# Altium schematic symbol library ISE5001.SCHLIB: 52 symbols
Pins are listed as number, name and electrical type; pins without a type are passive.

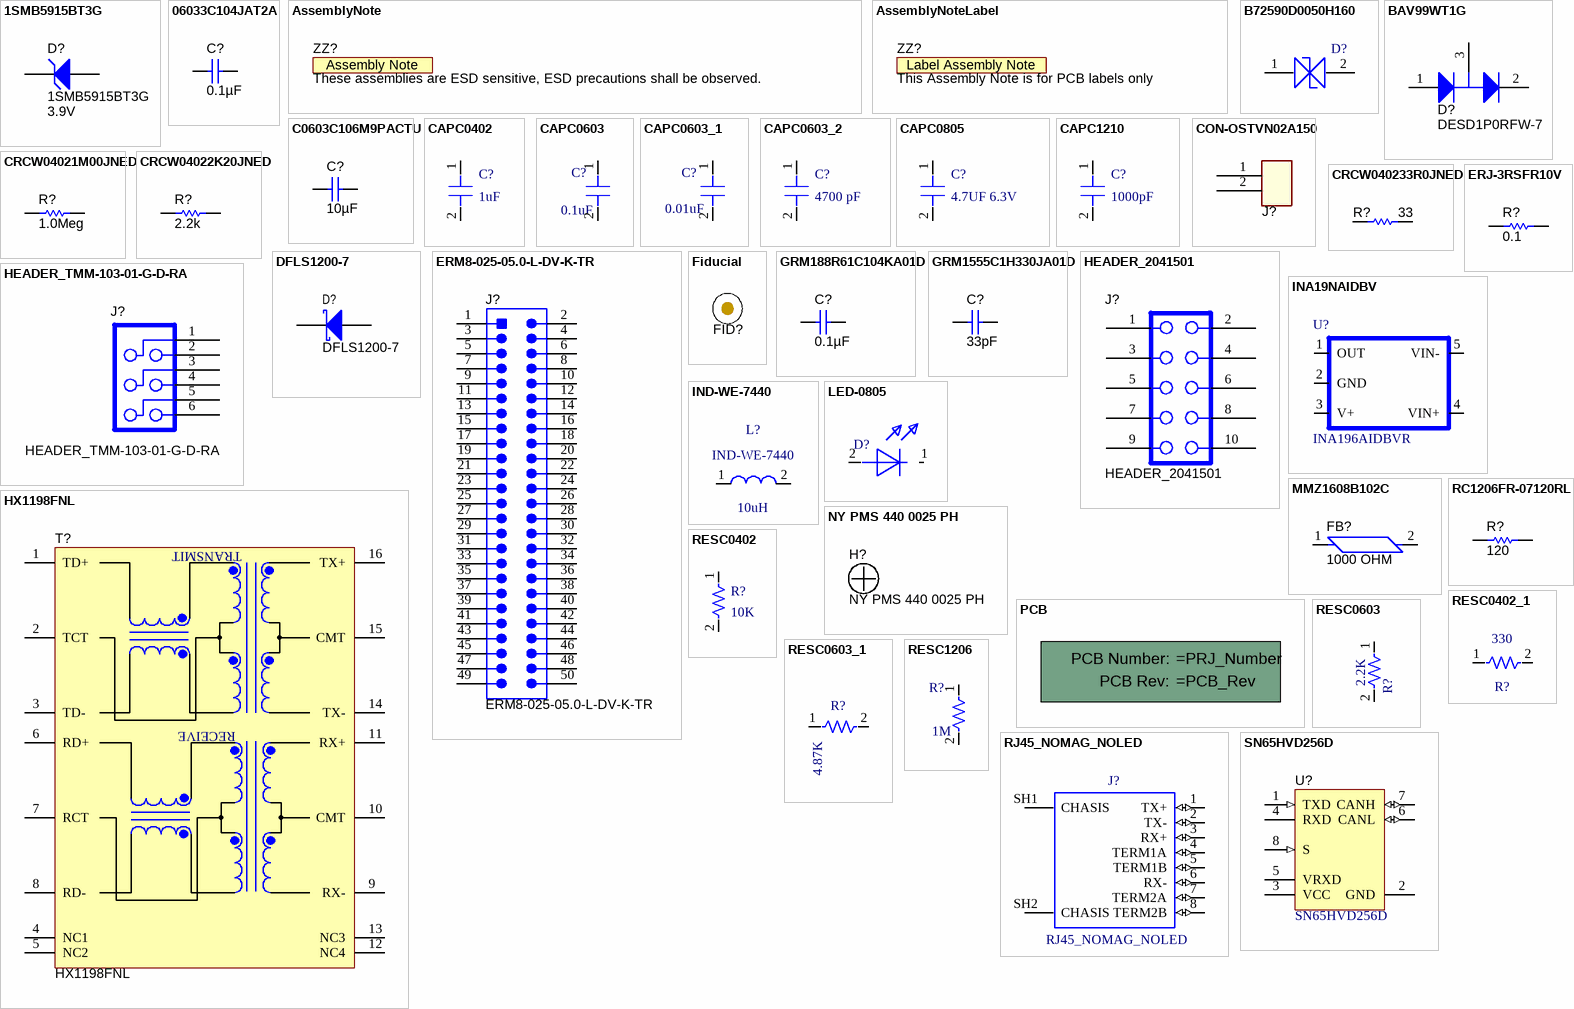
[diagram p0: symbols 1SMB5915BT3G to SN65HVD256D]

## 1SMB5915BT3G
designator D?  value 3.9V
Diode, Zener, 3.9V, 550mW, SMB; Manufacturer: ON Semiconductor; SymbolCreator: a0412235; U/M: EA; Power_W: 0.55; Vz_V: 3.9; Value1: 0.55W; RJA_CperW: 226
signal-integrity model Diode
footprint SMB
pins: 1 K, 2 A

## 06033C104JAT2A
designator C?  ValueDisplayed: 0.1µF  (hidden comment: 06033C104JAT2A)
CAP, CERM, 0.1uF, 25V, +/-5%, X7R, 0603; Manufacturer: AVX; Polarized: N; CompType: Capacitor; U/M: EA; Cap_F: 0.0000001; Tolerance_%: 5; ESR_Ohm: 0.05; Value1: 0.05 ohm; VDC_V: 25; TaMin_C: -55; TaMax_C: 125; Cap_Case: 0603
signal-integrity model Cap
simulation model Cap
footprint 0603
footprint 0603M
footprint 0603L
footprint 0603_HV
pins: 1, 2

## AssemblyNote
designator ZZ?, comment These assemblies are ESD sensitive, ESD precautions shall be observed.  (no BOM)
SymbolCreator: codlsc; CompType: AssemblyNote
footprint AssemblyNote

## AssemblyNoteLabel
designator ZZ?, comment This Assembly Note is for PCB labels only  (no BOM)
SymbolCreator: a0412235
footprint AssemblyNoteLabel

## B72590D0050H160
designator D?  (value not drawn)
Diode, 5.6V ESD Suppressor 0402; GNUM: G14-D0402-5V6-DAA; PCB DECAL: RESC0402N
footprint RESC0402N
pins: 1 (power), 2

## BAV99WT1G
designator D?, comment DESD1P0RFW-7
Diode, P-N, 70V, 0.2A, SOT-323; Manufacturer: Diodes Inc
footprint SOT-323
pins: 1 A, 2 K, 3 C
1 alternate drawing of the same symbol

## C0603C106M9PACTU
designator C?  ValueDisplayed: 10µF  (hidden comment: C0603C106M9PACTU)
CAP, CERM, 10uF, 6.3V, +/-20%, X5R, 0603; Manufacturer: Kemet; Polarized: N; CompType: Capacitor; U/M: EA; Cap_F: 0.00001; Tolerance_%: 20; ESR_Ohm: 0.004; Value1: 0.004 ohm; VDC_V: 6.3; IRMS_A: 8.9; TaMin_C: -55; TaMax_C: 85; Cap_Case: 0603
signal-integrity model Cap
simulation model Cap
footprint 0603
footprint 0603M
footprint 0603L
footprint 0603_HV
pins: 1, 2

## CAPC0402
designator C?  value 1uF  (hidden comment: CAPC0402)
Capacitor, 1uF , X5R, 10V, 0402; Part Number: C1005X5R1A105M050BB; PCB DECAL: CAPC0402N; GNUM: G10-C0402-C105-GCB
footprint 0402 (0402 from SM-752 data)
pins: 1, 2

## CAPC0603
designator C?  value 0.1uF  (hidden comment: CAPC0603)
Capacitor, 0.1uF 50V, 20% 0603 X7R; Part Number: C1608X7R1H104M; GNUM: G10-C0603-C104-ACA; PCB DECAL: CAPC0603L
footprint 0603 (0603 from SM-752 data)
pins: 1, 2

## CAPC0603_1
designator C?, comment value 0.01uF  (hidden comment: CAPC0603)
Capacitor, 0.01uF 25V, 10% 0402 X7R; Part Number: TMK105B7103KV-F; PCB DECAL: CAPC0402L; GNUM: G10-C0402-C103-BBA
footprint 0402 (0402 from SM-752 data)
pins: 1, 2

## CAPC0603_2
designator C?, comment value 4700 pF  (hidden comment: CAPC0603)
Capacitor, 4700pF, 2kV, 10%, X7R, 1812; Part Number: 1812GC472KAT1A; GNUM: G10-C1812-C472-ZBA; PCB DECAL: 1812MIL
footprint 1812
pins: 1, 2

## CAPC0805
designator C?  value 4.7UF 6.3V  (hidden comment: CAPC0805)
Capacitor, 4.7uF, 6.3V, 10% 0805, X5R; Part Number: JMK212BJ475KG-T; GNUM: G10-C0805-C475-DBB; Geometry.Height: 1.1mm; PCBL.Component: CHP;CAPC;1800;2200;250;750;1050;1450;1100; PCBL.Process: F;N;50;50;200;100;200;250;350;-50;0
footprint 0805 (0805 from SM-752 data)
pins: 1, 2

## CAPC1210
designator C?  value 1000pF  (hidden comment: CAPC1210)
CAP CER 1000PF 2KV 20% X7R 1210; Part Number: C1210C102MGRACTU; GNUM: G10-C1210-C102-ZCA
footprint 1210 (1210 from SM-752 data)
pins: 1, 2

## CON-OSTVN02A150
designator J?  (value not drawn)
Terminal Block, 4x1, 2.54mm, TH; Manufacturer: On Shore Technology Inc; SymbolCreator: x0120606
footprint CN2_MTB_P100_PD80_D1.1_S5.54X6.5_STACK
pins: 1, 2

## CRCW04021M00JNED
designator R?  value 1.0Meg  (hidden comment: CRCW04021M00JNED)
RES, 1.0Meg ohm, 5%, 0.063W, 0402; Manufacturer: Vishay-Dale; CompType: Resistor; Res_ohm: 1000000; Value_Code: 1M00; Tolerance_%: 5; Power_W: 0.063; VDC_V: 50; TempCo: 200 ppm/C; EIA_Code: E24; U/M: EA
signal-integrity model Resistor
simulation model Resistor
footprint 0402
footprint 0402M
footprint 0402L
footprint 0402S
pins: 1, 2

## CRCW04022K20JNED
designator R?  value 2.2k  (hidden comment: CRCW04022K20JNED)
RES, 2.2k ohm, 5%, 0.063W, 0402; Manufacturer: Vishay-Dale; CompType: Resistor; Res_ohm: 2200; Value_Code: 2k20; Tolerance_%: 5; Power_W: 0.063; VDC_V: 50; TempCo: 200 ppm/C; EIA_Code: E24; U/M: EA
signal-integrity model Resistor
simulation model Resistor
footprint 0402
footprint 0402M
footprint 0402L
footprint 0402S
pins: 1, 2

## CRCW040233R0JNED
designator R?  value 33  (hidden comment: CRCW040233R0JNED)
RES, 33 ohm, 5%, 0.063W, 0402; Manufacturer: Vishay-Dale; CompType: Resistor; Value_Code: 33R0; Tolerance_%: 5; Power_W: 0.063; VDC_V: 50; TempCo: 200 ppm/C; EIA_Code: E24; U/M: EA
signal-integrity model Resistor
simulation model Resistor
footprint 0402
footprint 0402M
footprint 0402L
footprint 0402S
pins: 1, 2

## DFLS1200-7
designator D?
Diode, Schottky, 200V, 1A, PowerDI123; Manufacturer: Diodes Inc.; U/M: EA; Vf_V: 0.85; Value2: 0.85V; Io_A: 1; Vr_V: 200; TJmax_C: 175; RJC_CperW: 7
signal-integrity model Diode
simulation model DI_DFLS1200
footprint powerDI123
pins: 1 K, 2 A

## ERJ-3RSFR10V
designator R?  value 0.1  (hidden comment: ERJ-3RSFR10V)
RES, 0.1 ohm, 1%, 0.1W, 0603; Manufacturer: Panasonic; CompType: Resistor; Value_Code: R100; Tolerance_%: 1; TempCo: 300 ppm/C; EIA_Code: E96; U/M: EA
signal-integrity model Resistor
simulation model Resistor
footprint 0603 (0603 from SM-752 data)
pins: 1, 2

## ERM8-025-05.0-L-DV-K-TR
designator J?
CONN MICRO HS TERM STRP HDR 50 POS; Manufacturer: Samtec; SymbolCreator: a0799628; CompType: Header; U/M: EA
footprint SAMTEC_ERM8-025-05_0-L-DV-K-TR
pins: 1, 2, 3, 4, 5, 6, 7, 8, 9, 10, 11, 12, 13, 14, 15, 16, 17, 18, 19, 20, 21, 22, 23, 24, 25, 26, 27, 28, 29, 30, 31, 32, 33, 34, 35, 36, 37, 38, 39, 40, 41, 42, 43, 44, 45, 46, 47, 48, 49, 50

## Fiducial
designator FID?  (value not drawn)
Fiducial mark.  There is nothing to buy or mount.; SymbolCreator: codlsc
footprint Fiducial10-30
footprint Fiducial10-20
footprint Fiducial15-30
footprint Fiducial20-40
footprint Fiducial6.4-20
footprint Fiducial10-30_TopLayerKeepOutOnly
footprint Fiducial6.4-20_TopLayerKeepOutOnly
footprint Fiducial10-20_TopLayerKeepOutOnly
footprint Fiducial15-30_TopLayerKeepOutOnly
footprint Fiducial20-40_TopLayerKeepOutOnly

## GRM188R61C104KA01D
designator C?  ValueDisplayed: 0.1µF  (hidden comment: GRM188R61C104KA01D)
CAP, CERM, 0.1uF, 16V, +/-10%, X5R, 0603; Manufacturer: MuRata; Polarized: N; CompType: Capacitor; U/M: EA; Cap_F: 0.0000001; Tolerance_%: 10; Value1: Unknown; VDC_V: 16; TaMin_C: -55; TaMax_C: 85; Cap_Case: 0603
signal-integrity model Cap
simulation model Cap
footprint 0603
footprint 0603M
footprint 0603L
footprint 0603_HV
pins: 1, 2

## GRM1555C1H330JA01D
designator C?  ValueDisplayed: 33pF  (hidden comment: GRM1555C1H330JA01D)
CAP, CERM, 33pF, 50V, +/-5%, C0G/NP0, 0402; Manufacturer: MuRata; Polarized: N; CompType: Capacitor; U/M: EA; Cap_F: 0.000000000033; Tolerance_%: 5; Value1: Unknown; VDC_V: 50; TaMin_C: -55; TaMax_C: 125; Cap_Case: 0402
signal-integrity model Cap
simulation model Cap
footprint 0402
footprint 0402M
footprint 0402L
footprint 0402S
pins: 1, 2

## HEADER_2041501
designator J?
Header, 2X5 2mm spacing; PartNumber: M22-2020505; Manufacturer: Harwin Inc; Area: 55 mm
footprint HDR_2X5-2MM
pins: 1, 2, 3, 4, 5, 6, 7, 8, 9, 10

## HEADER_TMM-103-01-G-D-RA
designator J?
Header, 2mm, Low Profile 2x3; Manufacturer: Samtec; Area: 57.75 mm
footprint HEADER_TMM-103[2X]
pins: 1, 2, 3, 4, 5, 6

## HX1198FNL
designator T?
TRANSFORMER, MDL, XFMR SGL ETHR LAN, SOIC-16; Manufacturer: PULSE ELECTRONICS; SymbolCreator: x0199378
footprint XFMR_ HX1198FNL (TRANSFORMER, MODULE XFMR, 16-SOIC)
pins: 1 TD+, 2 TCT, 3 TD-, 4 NC1, 5 NC2, 6 RD+, 7 RCT, 8 RD-, 9 RX-, 10 CMT, 11 RX+, 12 NC4, 13 NC3, 14 TX-, 15 CMT, 16 TX+

## INA19NAIDBV
designator U?, comment INA196AIDBVR
IC, Current Shunt Monitor, -16V to 80V Common-Mode Range; Manufacturer: TI; Alternate Manufacturer: None; Area: 23200; Value: INA196/8AIDBV; PCB DECAL: REF3230AIDBVT
footprint SOT23-5P
pins: 1 OUT, 2 GND, 3 V+, 4 VIN+, 5 VIN-

## IND-WE-7440
designator L?  value 10uH
Inductor 10uH, SMD 2.8x2.8mm, 0.5A, 0.47 Ohm; Part Number: 744029100; GNUM: G12-SM2X2-I100-ADA; PCB DECAL: IND-WE-2M8
footprint IND_744029100 (INDUCTOR , SMD 2.8X2.8MM)
pins: 1, 2

## LED-0805
designator D?  (value not drawn)
LED AMBER CLEAR 0805 SMD; Manufacturer #1: LITE-ON; Part Number: LTST-C170AKT; PCB DECAL: DIOC0805N; GNUM: G14-D0805-AMB0-AAA; Description: SMT LED IN 0805 PACK
footprint DIOC0805N
pins: 1, 2

## MMZ1608B102C
designator FB?, comment 1000 OHM
FERRITE CHIP 1000 OHM 300MA 0603; PartNumber: MMZ1608B102C; Manufacturer: TDK Corporation; CompType: Ferrite Bead
footprint 0603L (0603 from SM-752 data)
pins: 1, 2

## NY PMS 440 0025 PH
designator H?
Machine Screw, Round, #4-40 x 1/4, Nylon, Philips panhead; Manufacturer: B&F Fastener Supply; CompType: Hardware; SymbolCreator: codlsc; U/M: EA
footprint MH3.2_H5_W6_KO8_STARHEAD

## PCB
designator !PCB?, comment Printed Circuit Board  (value not drawn)  (mechanical)
Manufacturer: Any; SymbolCreator: a0412235; CompType: PCB
1 alternate drawing of the same symbol

## RC1206FR-07120RL
designator R?  value 120  (hidden comment: RC1206FR-07120RL)
RES, 120 ohm, 1%, 0.25W, 1206; Manufacturer: Yageo America; CompType: Resistor; Value_Code: 120R; Tolerance_%: 1; Power_W: 0.25; VDC_V: 200; TempCo: 100 ppm/C; U/M: EA
signal-integrity model Resistor
simulation model Resistor
footprint 1206
footprint 1206M
footprint 1206L
pins: 1, 2

## RESC0402
designator R?  value 10K  (hidden comment: RESC0402)
Resistor, 10k ohm, 1/10W, 5%, 0402 Thick Film; Manufacturer #1: Generic; Part Number: RC0402FR-0710KL; Also Known As: 0402; Description: Resistor,Chip;1.00mm L X 0.5mm W X 0.35mm H; Geometry.Height: 0.35mm; PCBL.Component: CHP;RESC;1500;1700;150;400;700;950;600; PCBL.Process: F;N;50;50;200;100;200;250;350;-50;0; PCB DECAL: RESC0402N; GNUM: G11-R0402-1002-AAA
footprint 0402 (0402 from SM-752 data)
pins: 1, 2

## RESC0402_1
designator R?, comment value 330  (hidden comment: RESC0402)
Resistor, 330 ohm, 1/10W, 5%, 0402; Manufacturer #1: Generic; Part Number: RC0402FR-07330RL; Also Known As: 0402; Description: Resistor,Chip;1.00mm L X 0.5mm W X 0.35mm H; Geometry.Height: 0.35mm; PCBL.Component: CHP;RESC;1500;1700;150;400;700;950;600; PCBL.Process: F;N;50;50;200;100;200;250;350;-50;0; PCB DECAL: RESC0402N; GNUM: G11-R0402-3300-AAA
footprint 0402 (0402 from SM-752 data)
pins: 1, 2

## RESC0603
designator R?  value 2.2K  (hidden comment: RESC0603)
Resistor, 2.2K OHM 1/10W 5% 0603 SMD; Manufacturer #1: Generic; Part Number: CRCW06032K20JNEA; PCB DECAL: RESC0603N; GNUM: G11-R0603-R222-AAA; Also Known As: 0603; Description: Resistor,Chip;1.60mm L X 0.83mm W X 0.60mm H; Geometry.Height: 0.6mm; PCBL.Component: CHP;RESC;1500;1700;150;400;700;950;600; PCBL.Process: F;N;50;50;200;100;200;250;350;-50;0
footprint 0603 (0603 from SM-752 data)
pins: 1, 2

## RESC0603_1
designator R?, comment value 4.87K  (hidden comment: RESC0603)
Resistor, 4.87K Ohm, 1/10W, 1%, SMD, Thick; Manufacturer #1: Generic; Part Number: ERJ-3EKF4871V; Also Known As: 0603; Description: Resistor,Chip;1.60mm L X 0.83mm W X 0.60mm H; Geometry.Height: 0.6mm; PCBL.Component: CHP;RESC;1500;1700;150;400;700;950;600; PCBL.Process: F;N;50;50;200;100;200;250;350;-50;0; PCB DECAL: RESC0603N; GNUM: G11-R0603-4871-ABA
footprint 0603 (0603 from SM-752 data)
pins: 1, 2

## RESC1206
designator R?  value 1M  (hidden comment: RESC1206)
RES 1M OHM 5% 1206 TF; Manufacturer #1: IPC SM-782; Part Number: ERJ-8GEYJ105V; Description: SURFACE MOUNT RESISTOR OR CAPACITOR 0.062 X 0.126 INCHES; PCB DECAL: 1206; GNUM: G11-R1206-R105-CAA
footprint 1206
pins: 1, 2

## RJ45_NOMAG_NOLED
designator J?
Connector, RJ45 NO MAG, shielded THRU HOLE; Part Number: 6116526-1; PCB DECAL: 406541; GNUM: G20-8RJ45-ENET-AAA
footprint TE_6116526-1 (CONNECTOR, MODULAR JACK SHIELDED R/A, THRU-8 PIN)
pins: 1 TX+ (io), 2 TX- (io), 3 RX+ (io), 4 TERM1A (io), 5 TERM1B (io), 6 RX- (io), 7 TERM2A (io), 8 TERM2B (io), SH1 CHASIS, SH2 CHASIS

## SN65HVD256D
designator U?
CAN Transceiver with Fast Loop Times for Highly Loaded Networks, 85 mA, 5 V, -40 to 125 degC, 8-pin SOIC (D), Green (RoHS & no Sb/Br); Manufacturer: Texas Instruments; Alternate Manufacturer: None; Alternate PartNumber: Equivalent; Drivers Per Package: 1; Bus Fault Voltage(V): -27 to 40; ICC(Max)(mA): 85; Supply Voltage(s)(V): 5; Rating: Catalog
footprint D0008A_N (SOIC, 8-Leads, Body 4.9x3.9mm, Pitch 1.27mm, IPC Medium Density)
footprint D0008A_L (SOIC, 8-Leads, Body 4.9x3.9mm, Pitch 1.27mm, IPC High Density)
footprint D0008A_M (SOIC, 8-Leads, Body 4.9x3.9mm, Pitch 1.27mm, IPC Low Density)
pins: 1 TXD (in) "CAN transmit data input (LOW for dominant and HIGH for recessive bus states)", 2 GND (power) "Ground connection", 3 VCC (power) "Transceiver 5V supply voltage", 4 RXD (hiz) "CAN receive data output (LOW for dominant and HIGH for recessive bus states)", 5 VRXD (power) "RXD output supply voltage", 6 CANL (io) "Low level CAN bus line", 7 CANH (io) "High level CAN bus line", 8 S (in) "S (Silent Mode) select pin (active high)"

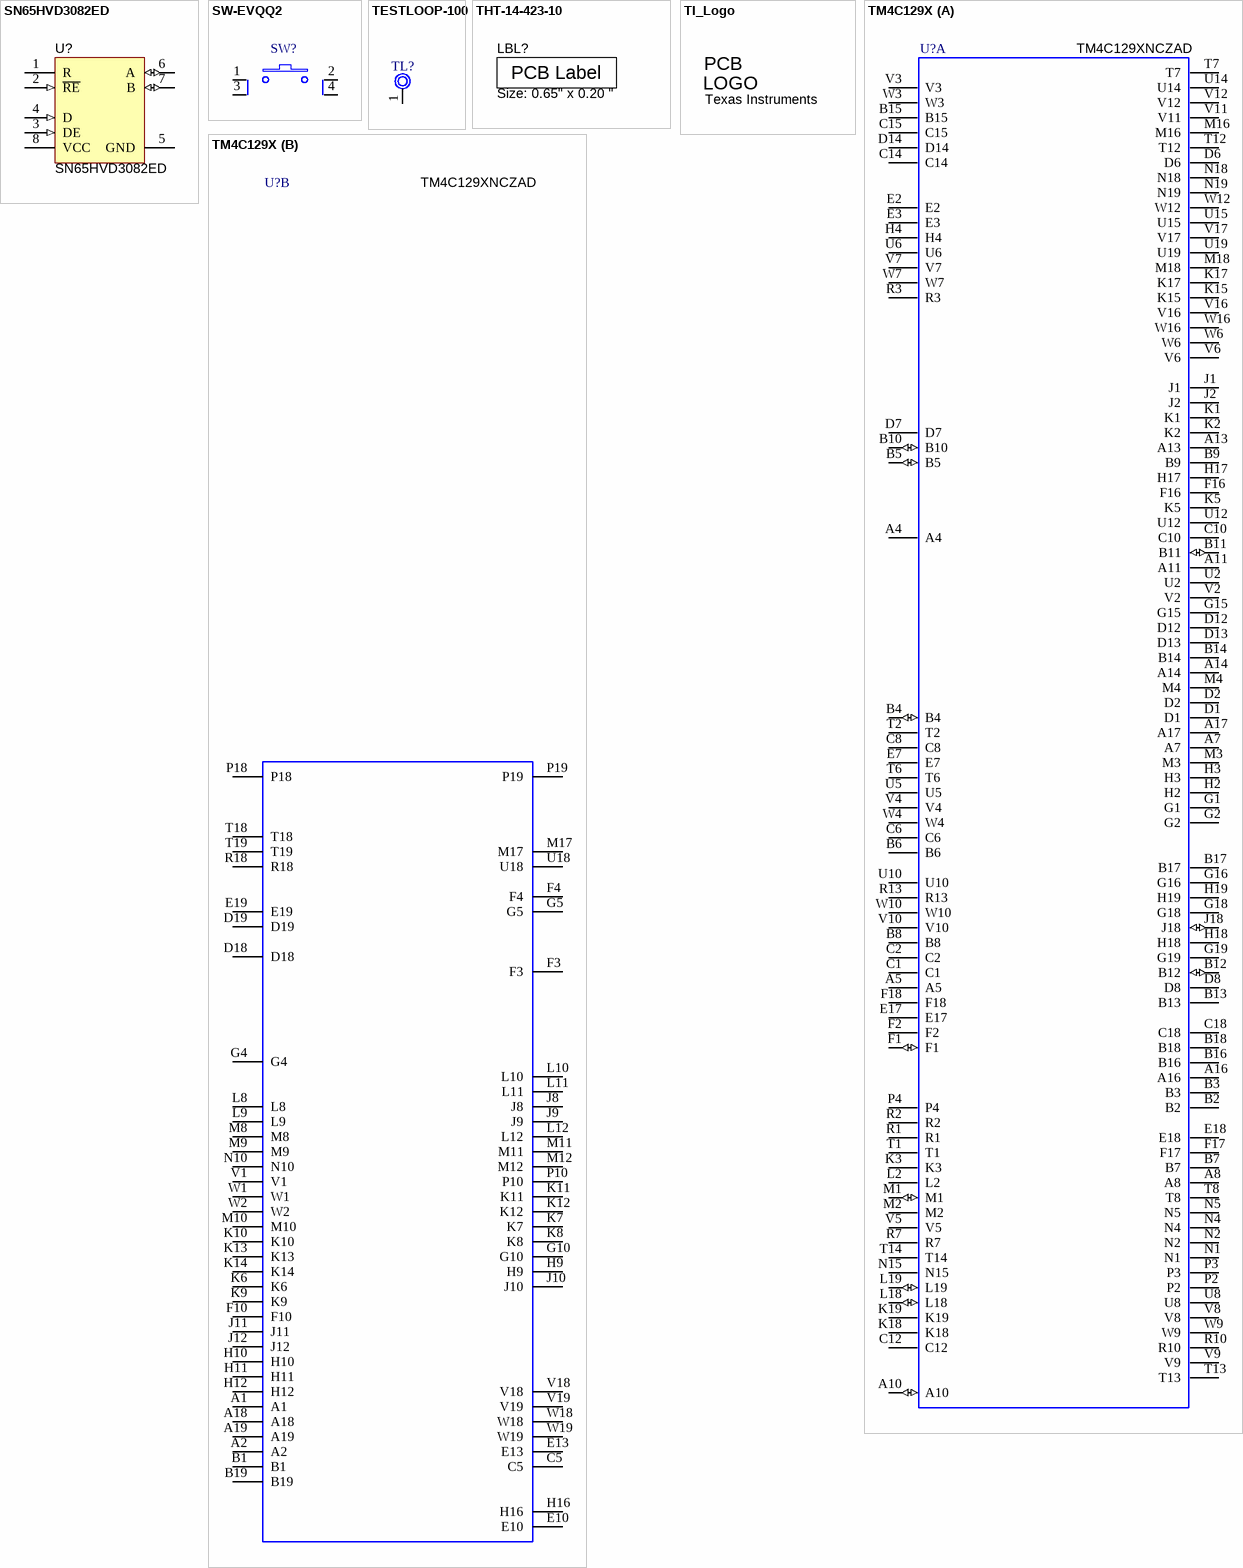
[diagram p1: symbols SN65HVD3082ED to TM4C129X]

## SN65HVD3082ED
designator U?
IC, RS485 TRANSCEIVER LP, 8-SOIC; Manufacturer: TEXAS INSTRUMENTS; CompType: LOW-POWER RS-485 TRANSCEIVER; SymbolCreator: x0199378
footprint D0008A_N (SOIC, 8-Leads, Body 4.9x3.9mm, Pitch 1.27mm, IPC Medium Density)
pins: 1 R (hiz), 2 ~{RE} (in), 3 DE (in), 4 D (in), 5 GND (power), 6 A (io), 7 B (io), 8 VCC (power)

## SW-EVQQ2
designator SW?  (value not drawn)
Switch, Tact 6mm SMT, 160gf; Manufacturer #1: Panasonic; Part Number: B3S-1000; Description: Switch, Tact 6mm SMT, 50gf; GNUM: G21-4P6MM-B3S1-AAA
footprint SW-EVQQ2
pins: 1, 2, 3, 4

## TESTLOOP-100
designator TL?  (value not drawn)
Terminal, Test Point Miniature Loop, Red, T-Hole; Part Number: 5000; Manufacturer #1: Keystone Electronics; Description: Test loop, Miniature White, Through-hole; PCB DECAL: PAD70H39; GNUM: G20-K5000-TP00-AAA
footprint PAD70H39
pins: 1

## THT-14-423-10
designator LBL?, comment Size: 0.65" x 0.20 "
Thermal Transfer Printable Labels, 0.650" W x 0.200" H - 10,000 per roll; Manufacturer: Brady; PartNumber: THT-14-423-10; SymbolCreator: a0412235; CompType: Label
footprint Label_650x200

## TI_Logo
designator Logo?, comment Texas Instruments  (no BOM)
Texas Instrument Corporate Signature; SymbolCreator: codlsc
footprint TI_Stacked_SolderMask_Medium
footprint TI_Stacked_SolderMask_Small
footprint TI_Stacked_Overlay_Medium
footprint TI_Stacked_Overlay_Small
footprint TI_Horizontal_SolderMask_Medium
footprint TI_Horizontal_SolderMask_Small
footprint TI_Horizontal_Overlay_Medium
footprint TI_Horizontal_Overlay_Small
footprint TI_Symbol_SolderMask_Small
footprint TI_Symbol_Overlay_Medium
footprint TI_Symbol_Overlay_Small
footprint TI_Symbol_SolderMask_Medium

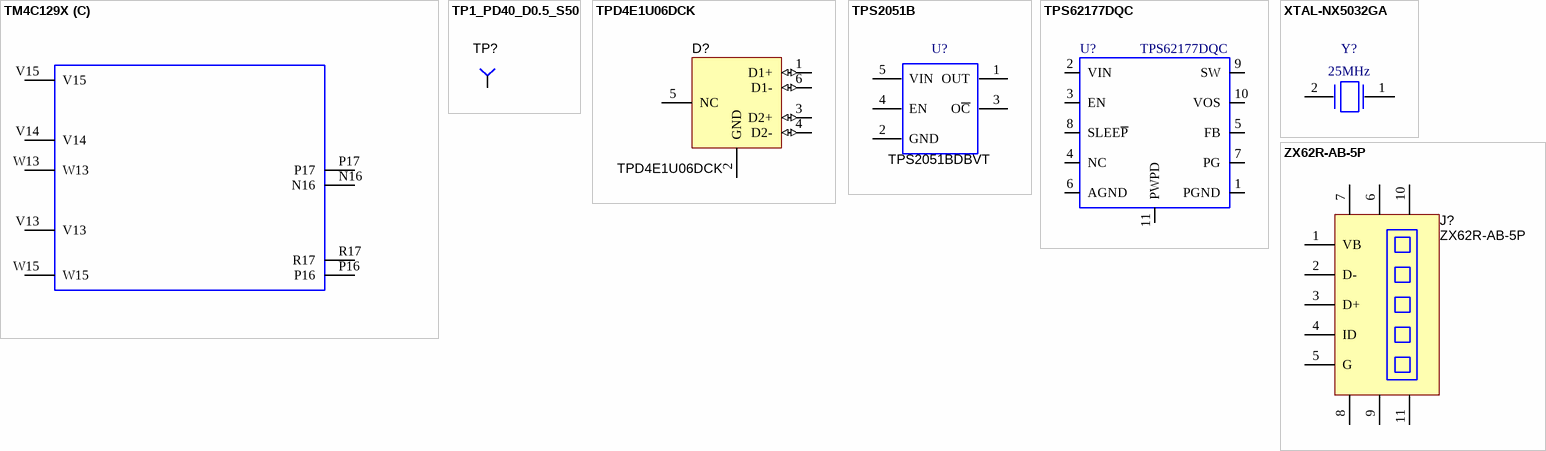
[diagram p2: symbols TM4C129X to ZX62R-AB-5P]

## TM4C129X
designator U?  Part Number: TM4C129XNCZAD  (hidden comment: TM4C129X)
Stellaris MCU TM4C129XNCZAD 212 BGA, super; GNUM: G50-BG212-C129-ALI; PCB DECAL: BGA19X19-05MM-T1; Geometry.Height: 50.00mil
footprint BGA212C50P19X19_1000X1000X100
part A pins: A4, A5, A7, A8, A10 (io), A11, A13, A14, A16, A17, B2, B3, B4 (io), B5 (io), B6, B7, B8, B9, B10 (io), B11 (io), B12 (io), B13, B14, B15, B16, B17, B18, C1, C2, C6, C8, C10, C12, C14, C15, C18, D1, D2, D6, D7, D8, D12, D13, D14, E2, E3, E7, E17, E18, F1 (io), F2, F16, F17, F18, G1, G2, G15, G16, G18, G19, H2, H3, H4, H17, H18, H19, J1, J2, J18 (io), K1, K2, K3, K5, K15, K17, K18, K19, L2, L18 (io), L19 (io), M1 (io), M2, M3, M4, M16, M18, N1, N2, N4, N5, N15, N18, N19, P2, P3, P4, R1, R2, R3, R7, R10, R13, T1, T2, T6, T7, T8, T12, T13, T14, U2, U5, U6, U8, U10, U12, U14, U15, U19, V2, V3, V4, V5, V6, V7, V8, V9, V10, V11, V12, V16, V17, W3, W4, W6, W7, W9, W10, W12, W16
part B pins: A1, A2, A18, A19, B1, B19, C5, D18, D19, E10 (power), E13, E19, F3 (power), F4 (power), F10, G4, G5, G10 (power), H9 (power), H10, H11, H12, H16 (power), J8 (power), J9 (power), J10 (power), J11, J12, K6, K7 (power), K8 (power), K9, K10, K11 (power), K12 (power), K13, K14, L8, L9, L10 (power), L11 (power), L12 (power), M8, M9, M10, M11 (power), M12 (power), M17, N10, P10 (power), P18, P19 (power), R18, T18, T19, U18, V1, V18, V19, W1, W2, W18, W19
part C pins: N16 (power), P16, P17 (power), R17, V13, V14, V15, W13, W15

## TP1_PD40_D0.5_S50
designator TP?  (value not drawn)
Test Point 40mil pad 20mil drill; Manufacturer: STD; Description: Test Point, O.040 Hole; Value: STD
footprint TP-040_RND
footprint TP1_PD40_D0.5_S50
pins: 1

## TPD4E1U06DCK
designator D?
Quad Channel High Speed ESD Protection Device, DCK0006A; Alternate Manufacturer: None; Manufacturer: Texas Instruments; SymbolCreator: a0411947; CompType: IC; U/M: EA
footprint DCK0006A_N
footprint DCK0006A_M
footprint DCK0006A_L
pins: 1 D1+ (io), 2 GND (power), 3 D2+ (io), 4 D2- (io), 5 NC, 6 D1- (io)

## TPS2051B
designator U?  Part Number: TPS2051BDBVT  (hidden comment: TPS2051B)
Load Switch, 5.5V, SOT23-5, TPS2051BDBV; PCB DECAL: DBV5; GNUM: G41-SOT23-2051-AAA
footprint DBV5
pins: 1 OUT, 2 GND (power), 3 O~{C}, 4 EN, 5 VIN (power)

## TPS62177DQC
designator U?
Regulator, Step Down  3.3V, 0.5A; GNUM: G51-DQC10-2177-AAA; PCB DECAL: DQC-10P
footprint DQC-10P
pins: 1 PGND, 2 VIN, 3 EN, 4 NC, 5 FB, 6 AGND, 7 PG, 8 SLEE~{P}, 9 SW, 10 VOS, 11 PWPD

## XTAL-NX5032GA
designator Y?  value 25MHz  (hidden comment: XTAL-NX5032GA)
Crystal, 25.00MHz 5.0x3.2mm SMT; Part Number: 445I23D25M00000; Description: Crystal, 16.00MHz 5.0x3.2mm SMT; GNUM: G15-5X3P2-2506-AAA
footprint XTAL-NX5032GA
pins: 1, 2

## ZX62R-AB-5P
designator J?
Connector, USB micro AB Receptacle Reversed SMD; Manufacturer: HIROSE ELECTRIC CO. LTD.; SymbolCreator: x0199378
footprint CON-USB-MICRO-REV
pins: 1 VB, 2 D-, 3 D+, 4 ID, 5 G, 6, 7, 8, 9, 10, 11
